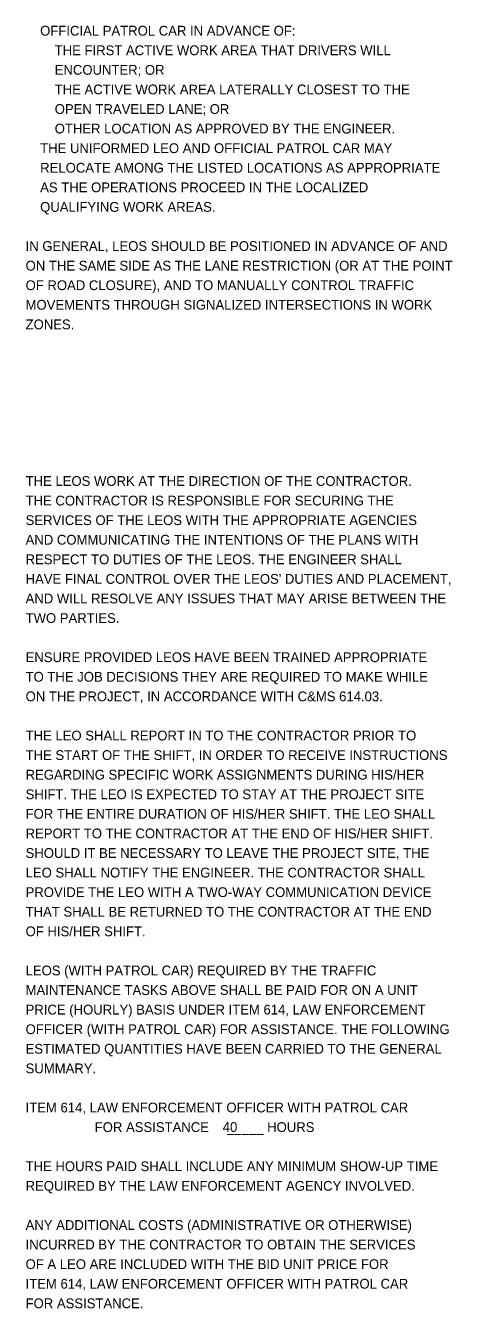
# Model space of a CAD drawing. Extents: x -40 to 107, y -47 to 37.
# Drawn here: x 100.78 to 106.88, y -46.99 to -28.64 of the extents above; entities that cross this region are included whole.
import ezdxf

# ---------------------------------------------------------------- set-up
doc = ezdxf.new("R2010")
doc.units = 0
doc.layers.add('SH_Text', color=7, linetype='Continuous')

msp = doc.modelspace()

# ---------------------------------------------------------------- texts
at = {"layer": 'SH_Text'}
for s, p in [('    OFFICIAL PATROL CAR IN ADVANCE OF:', (100.781, -28.785)), ('        THE FIRST ACTIVE WORK AREA THAT DRIVERS WILL', (100.781, -29.065)), ('        ENCOUNTER; OR', (100.781, -29.345)), ('        THE ACTIVE WORK AREA LATERALLY CLOSEST TO THE', (100.781, -29.625)), ('        OPEN TRAVELED LANE; OR', (100.781, -29.905)), ('        OTHER LOCATION AS APPROVED BY THE ENGINEER.', (100.781, -30.185)), ('    THE UNIFORMED LEO AND OFFICIAL PATROL CAR MAY', (100.781, -30.465)), ('    RELOCATE AMONG THE LISTED LOCATIONS AS APPROPRIATE', (100.781, -30.745)), ('    AS THE OPERATIONS PROCEED IN THE LOCALIZED', (100.781, -31.025)), ('    QUALIFYING WORK AREAS.', (100.781, -31.305)), ('IN GENERAL, LEOS SHOULD BE POSITIONED IN ADVANCE OF AND', (100.781, -31.865)), ('ON THE SAME SIDE AS THE LANE RESTRICTION (OR AT THE POINT', (100.781, -32.145)), ('OF ROAD CLOSURE), AND TO MANUALLY CONTROL TRAFFIC', (100.781, -32.425)), ('MOVEMENTS THROUGH SIGNALIZED INTERSECTIONS IN WORK', (100.781, -32.705)), ('ZONES.', (100.781, -32.985)), ('THE LEOS WORK AT THE DIRECTION OF THE CONTRACTOR.', (100.781, -35.225)), ('THE CONTRACTOR IS RESPONSIBLE FOR SECURING THE', (100.781, -35.505)), ('SERVICES OF THE LEOS WITH THE APPROPRIATE AGENCIES', (100.781, -35.785)), ('AND COMMUNICATING THE INTENTIONS OF THE PLANS WITH', (100.781, -36.065)), ('RESPECT TO DUTIES OF THE LEOS. THE ENGINEER SHALL', (100.781, -36.345)), ("HAVE FINAL CONTROL OVER THE LEOS' DUTIES AND PLACEMENT,", (100.781, -36.625)), ('AND WILL RESOLVE ANY ISSUES THAT MAY ARISE BETWEEN THE', (100.781, -36.905)), ('TWO PARTIES.', (100.781, -37.185)), ('ENSURE PROVIDED LEOS HAVE BEEN TRAINED APPROPRIATE', (100.781, -37.745)), ('TO THE JOB DECISIONS THEY ARE REQUIRED TO MAKE WHILE', (100.781, -38.025)), ('ON THE PROJECT, IN ACCORDANCE WITH C&MS 614.03.', (100.781, -38.305)), ('THE LEO SHALL REPORT IN TO THE CONTRACTOR PRIOR TO', (100.781, -38.865)), ('THE START OF THE SHIFT, IN ORDER TO RECEIVE INSTRUCTIONS', (100.781, -39.145)), ('REGARDING SPECIFIC WORK ASSIGNMENTS DURING HIS/HER', (100.781, -39.425)), ('SHIFT. THE LEO IS EXPECTED TO STAY AT THE PROJECT SITE', (100.781, -39.705)), ('FOR THE ENTIRE DURATION OF HIS/HER SHIFT. THE LEO SHALL', (100.781, -39.985)), ('REPORT TO THE CONTRACTOR AT THE END OF HIS/HER SHIFT.', (100.781, -40.265)), ('SHOULD IT BE NECESSARY TO LEAVE THE PROJECT SITE, THE', (100.781, -40.545)), ('LEO SHALL NOTIFY THE ENGINEER. THE CONTRACTOR SHALL', (100.781, -40.825)), ('PROVIDE THE LEO WITH A TWO-WAY COMMUNICATION DEVICE', (100.781, -41.105)), ('THAT SHALL BE RETURNED TO THE CONTRACTOR AT THE END', (100.781, -41.385)), ('OF HIS/HER SHIFT.', (100.781, -41.665)), ('LEOS (WITH PATROL CAR) REQUIRED BY THE TRAFFIC', (100.781, -42.225)), ('MAINTENANCE TASKS ABOVE SHALL BE PAID FOR ON A UNIT', (100.781, -42.505)), ('PRICE (HOURLY) BASIS UNDER ITEM 614, LAW ENFORCEMENT', (100.781, -42.785)), ('OFFICER (WITH PATROL CAR) FOR ASSISTANCE. THE FOLLOWING', (100.781, -43.065)), ('ESTIMATED QUANTITIES HAVE BEEN CARRIED TO THE GENERAL', (100.781, -43.345)), ('SUMMARY.', (100.781, -43.625)), ('ITEM 614, LAW ENFORCEMENT OFFICER WITH PATROL CAR', (100.781, -44.185)), ('                   FOR ASSISTANCE     _____ HOURS', (100.781, -44.465)), ('40', (103.6, -44.463)), ('THE HOURS PAID SHALL INCLUDE ANY MINIMUM SHOW-UP TIME', (100.781, -45.025)), ('REQUIRED BY THE LAW ENFORCEMENT AGENCY INVOLVED.', (100.781, -45.305)), ('ANY ADDITIONAL COSTS (ADMINISTRATIVE OR OTHERWISE)', (100.781, -45.865)), ('INCURRED BY THE CONTRACTOR TO OBTAIN THE SERVICES', (100.781, -46.145)), ('OF A LEO ARE INCLUDED WITH THE BID UNIT PRICE FOR', (100.781, -46.425)), ('ITEM 614, LAW ENFORCEMENT OFFICER WITH PATROL CAR', (100.781, -46.705)), ('FOR ASSISTANCE.', (100.781, -46.985))]:
    msp.add_text(s, height=0.14, dxfattribs=at).set_placement(p)

doc.saveas('drawing.dxf')
